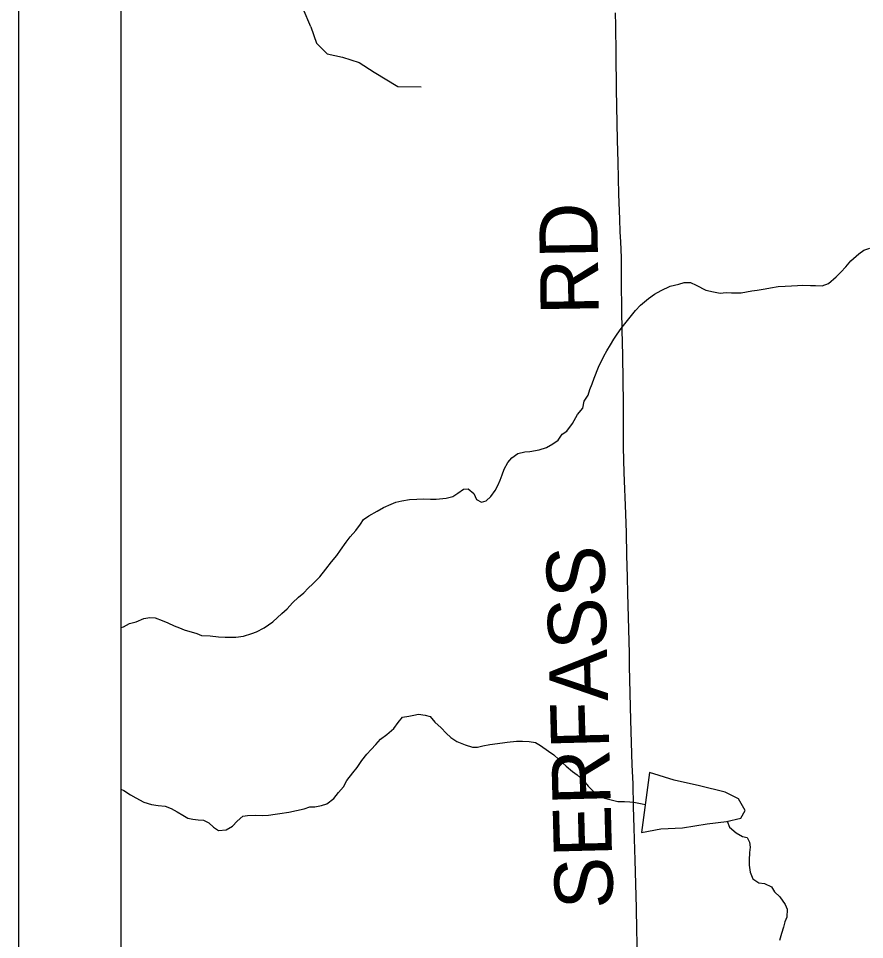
# Model space of a CAD drawing. Extents: x 0 to 34, y -5 to 22.
# Drawn here: x 2 to 2.826, y 15.62 to 16.518 of the extents above; entities that cross this region are included whole.
import ezdxf

# ---------------------------------------------------------------- set-up
doc = ezdxf.new("R2010")
doc.units = 0
for name, color, linetype in [('GM_X_Minor_Lake', 7, 'Continuous'), ('GM_X_Minor_River', 7, 'Continuous'), ('GM_X_Township_Road', 7, 'Continuous'), ('GM_X_Township_Road_Text', 7, 'Continuous'), ('GM_X_US_Route', 7, 'Continuous'), ('SH_Cut_Line', 7, 'Continuous'), ('SH_Data', 7, 'Continuous')]:
    doc.layers.add(name, color=color, linetype=linetype)

msp = doc.modelspace()

# ---------------------------------------------------------------- linework, layer by layer
at = {"layer": 'GM_X_Minor_Lake'}
for points in [[(2.60818, 15.72399), (2.62712, 15.72755), (2.64835, 15.72847), (2.67222, 15.73246), (2.69116, 15.73488), (2.70517, 15.73803), (2.70929, 15.74566), (2.70276, 15.757), (2.68981, 15.76336), (2.66473, 15.76962), (2.64004, 15.77513), (2.61609, 15.78254)], [(2.61609, 15.78254), (2.60818, 15.72399)]]:
    msp.add_lwpolyline(points, dxfattribs=at)
at = {"layer": 'GM_X_Minor_River'}
for points in [[(2.28557, 16.51024), (2.27029, 16.54562), (2.26294, 16.55848), (2.25144, 16.56787), (2.23769, 16.57458), (2.22395, 16.57938), (2.21095, 16.58762)], [(2.28556, 16.51024), (2.29105, 16.49415), (2.30137, 16.48398), (2.31619, 16.48067), (2.33253, 16.47548), (2.34739, 16.4661), (2.37026, 16.45184), (2.39302, 16.45164)], [(2.47408, 16.07847), (2.47776, 16.08501), (2.48148, 16.08965), (2.48748, 16.09395), (2.4943, 16.0956), (2.49925, 16.0957), (2.50835, 16.0974), (2.51554, 16.09982), (2.52156, 16.10336), (2.52682, 16.10688), (2.5309, 16.11267), (2.5354, 16.1158), (2.54097, 16.12314), (2.54575, 16.13198), (2.55096, 16.13817), (2.55235, 16.14505), (2.55604, 16.15083), (2.55784, 16.15619), (2.56001, 16.16194), (2.56181, 16.1673), (2.56617, 16.17804), (2.57129, 16.1888), (2.57423, 16.19418), (2.57793, 16.19996), (2.58125, 16.20535), (2.58458, 16.21036), (2.58828, 16.21576), (2.592, 16.2204), (2.6024, 16.23354), (2.60725, 16.23858), (2.61512, 16.2452), (2.62074, 16.24949), (2.62753, 16.25305), (2.6362, 16.25702), (2.64454, 16.25908), (2.64984, 16.26071), (2.65592, 16.26082), (2.66168, 16.25827), (2.67092, 16.25312), (2.67856, 16.25174), (2.68505, 16.25034), (2.69076, 16.25083), (2.69609, 16.25056), (2.7056, 16.25074), (2.71585, 16.25246), (2.72116, 16.25332), (2.72875, 16.25461), (2.73406, 16.25547), (2.74165, 16.25675), (2.74849, 16.25727), (2.75458, 16.25738), (2.76028, 16.25787), (2.76522, 16.25797), (2.77322, 16.25774), (2.77817, 16.25783), (2.78465, 16.25758), (2.79069, 16.2596), (2.79818, 16.26621), (2.80266, 16.27086), (2.80751, 16.2759), (2.81234, 16.28171), (2.8202, 16.28871), (2.82508, 16.29222), (2.83113, 16.29424)], [(2.1, 15.92413), (2.1025, 15.92484), (2.10853, 15.928), (2.11497, 15.92964), (2.12252, 15.93283), (2.12822, 15.9337), (2.13355, 15.93342), (2.14045, 15.93089), (2.14582, 15.92871), (2.15197, 15.92578), (2.15734, 15.9236), (2.16194, 15.92179), (2.17419, 15.91822), (2.1788, 15.9164), (2.18718, 15.9158), (2.19519, 15.91482), (2.20167, 15.91456), (2.21232, 15.91476), (2.21954, 15.91566), (2.22787, 15.9181), (2.2324, 15.91971), (2.23994, 15.92366), (2.2482, 15.92953), (2.25718, 15.9377), (2.26242, 15.94236), (2.26763, 15.94817), (2.27324, 15.95361), (2.27848, 15.95789), (2.28296, 15.96254), (2.28744, 15.96682), (2.29417, 15.97342), (2.30011, 15.98114), (2.30568, 15.9881), (2.31089, 15.99428), (2.31422, 15.99968), (2.31977, 16.0074), (2.32387, 16.01242), (2.32945, 16.01862), (2.3339, 16.02479), (2.33686, 16.02942), (2.34212, 16.03294), (2.35002, 16.03766), (2.35642, 16.04121), (2.36397, 16.0444), (2.3685, 16.04639), (2.37419, 16.04764), (2.38178, 16.04892), (2.389, 16.04944), (2.39585, 16.04957), (2.40232, 16.04932), (2.40765, 16.04942), (2.41753, 16.05037), (2.42397, 16.05202), (2.42886, 16.05515), (2.43449, 16.05907), (2.43905, 16.05953), (2.44447, 16.05469), (2.44725, 16.04903), (2.45186, 16.04646), (2.45641, 16.04769), (2.46127, 16.05197), (2.46535, 16.05775), (2.46791, 16.06275), (2.4701, 16.06774), (2.47228, 16.07311), (2.47408, 16.07847)], [(2.1, 15.76632), (2.10294, 15.76501), (2.10949, 15.76095), (2.11449, 15.758), (2.12257, 15.75359), (2.12984, 15.75144), (2.13633, 15.75042), (2.1432, 15.74979), (2.14895, 15.74762), (2.1551, 15.74432), (2.1605, 15.74099), (2.1655, 15.73804), (2.17009, 15.73699), (2.17543, 15.73633), (2.18077, 15.73605), (2.18576, 15.73348), (2.19041, 15.72939), (2.19542, 15.72606), (2.20265, 15.72658), (2.20905, 15.73013), (2.21352, 15.73516), (2.21914, 15.73983), (2.22369, 15.74068), (2.23168, 15.74083), (2.23816, 15.74058), (2.24424, 15.74107), (2.25069, 15.74196), (2.25525, 15.74243), (2.26398, 15.74374), (2.27156, 15.7454), (2.27876, 15.74706), (2.28443, 15.74907), (2.28938, 15.74917), (2.29582, 15.75043), (2.30112, 15.75206), (2.30787, 15.75714), (2.31233, 15.76293), (2.31717, 15.76873), (2.32047, 15.77488), (2.32642, 15.78223), (2.3305, 15.78763), (2.33532, 15.7942), (2.34015, 15.80038), (2.34425, 15.80502), (2.34872, 15.81005), (2.35357, 15.8151), (2.35957, 15.81978), (2.36631, 15.82561), (2.37076, 15.83141), (2.37485, 15.83643), (2.38092, 15.83769), (2.38585, 15.83855), (2.3904, 15.83939), (2.39689, 15.83838), (2.40186, 15.83733), (2.40654, 15.83171), (2.41274, 15.82612), (2.41741, 15.82089), (2.42205, 15.81679), (2.42784, 15.81271), (2.4359, 15.80944), (2.44317, 15.8073), (2.44812, 15.80739), (2.45342, 15.80864)], [(2.45342, 15.80864), (2.46025, 15.80991), (2.4724, 15.81166), (2.47696, 15.81213), (2.48608, 15.81307), (2.49216, 15.81318), (2.49864, 15.81292), (2.50475, 15.8119), (2.50975, 15.80895), (2.51747, 15.80339), (2.52249, 15.79968), (2.52753, 15.79521), (2.5345, 15.78888), (2.54069, 15.78367), (2.54533, 15.78033), (2.55191, 15.77437), (2.5562, 15.76912), (2.56087, 15.76426), (2.56626, 15.76056), (2.57203, 15.75763), (2.57854, 15.75585), (2.58504, 15.75445), (2.59151, 15.7542), (2.59685, 15.75392), (2.60219, 15.75326), (2.60868, 15.75186), (2.61186, 15.75121)], [(2.69163, 15.73499), (2.69401, 15.72914), (2.70059, 15.72356), (2.70674, 15.72025), (2.71133, 15.71919), (2.7137, 15.71467), (2.71418, 15.70973), (2.71352, 15.70439), (2.71328, 15.69716), (2.71337, 15.69221), (2.71427, 15.68538), (2.71668, 15.67896), (2.72285, 15.67489), (2.72819, 15.67423), (2.7351, 15.67094), (2.73786, 15.66604), (2.74328, 15.6612), (2.74838, 15.65369), (2.75037, 15.64916), (2.75014, 15.64154), (2.74794, 15.63693), (2.7469, 15.63159), (2.74474, 15.62546), (2.74297, 15.61857)]]:
    msp.add_lwpolyline(points, dxfattribs=at)
at = {"layer": 'GM_X_Township_Road'}
msp.add_lwpolyline([(2.6049, 15.57916), (2.6037, 15.62882), (2.60319, 15.65056), (2.60198, 15.69714), (2.60099, 15.7282), (2.60049, 15.74955), (2.59989, 15.77145), (2.59922, 15.79005), (2.59786, 15.83352), (2.59656, 15.88628), (2.59646, 15.8987), (2.59473, 15.95749), (2.59443, 15.97313), (2.59388, 15.9948), (2.59344, 16.01631), (2.59276, 16.03491), (2.59134, 16.0752), (2.59053, 16.09985), (2.59047, 16.11911), (2.59062, 16.14327), (2.59034, 16.16513), (2.58991, 16.18957), (2.5892, 16.21445), (2.58906, 16.23293), (2.58871, 16.26154), (2.58852, 16.28502), (2.58786, 16.30051), (2.5875, 16.31007), (2.58715, 16.32259), (2.58615, 16.34696), (2.58537, 16.37802), (2.58473, 16.39951), (2.58372, 16.44932), (2.58345, 16.48348), (2.58302, 16.51141), (2.58282, 16.52382)], dxfattribs=at)
at = {"layer": 'GM_X_US_Route'}
msp.add_lwpolyline([(2.1, 16.52208), (2.1, 14.1), (6.15603, 14.1)], dxfattribs=at)
at = {"layer": 'SH_Cut_Line'}
msp.add_lwpolyline([(2.1, 16.52208), (2.1, 14.1), (6.15603, 14.1)], dxfattribs=at)
at = {"layer": 'SH_Data'}
for p, q in [((2, 21), (2, 14)), ((2.1, 20.9), (2.1, 14.1))]:
    msp.add_line(p, q, dxfattribs=at)

# ---------------------------------------------------------------- texts
at = {"layer": 'GM_X_Township_Road_Text'}
for s, rotation, p in [('RD', 90.93029, (2.56661, 16.22942)), ('SERFASS', 91.45958, (2.58076, 15.65001))]:
    msp.add_text(s, height=0.056818, rotation=rotation, dxfattribs=at).set_placement(p)

doc.saveas('drawing.dxf')
